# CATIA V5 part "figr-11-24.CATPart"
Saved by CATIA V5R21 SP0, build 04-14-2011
Part number: Part1
Bounding box of the stored display mesh (mm): x -89.703 to 75.958, y -127.286 to 108.862, z -26.487 to 19.815
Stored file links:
  D:\CATIA V5R21 E-RESOURCES\CATIA-V5R21\catia-v5r21-prt\c11-catia-v5r21-prt\c11-catia-v5r21-figr-11-24.CATPart
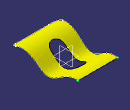
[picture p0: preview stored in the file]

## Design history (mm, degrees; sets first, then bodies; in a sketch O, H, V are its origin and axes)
Set1
  Extrude1: Element1 Sketch3, Lim1 86, Lim2 94, Direction yz-plane
  Sketch1 on xy-plane, origin (0, 0, 0), H (1, 0, 0), V (0, 1, 0)
    line L1 (64.3059, 108.8616) -> (75.9293, -106.0218)
    arc A1 centre (55.7837, -107.1115) radius 20.175 from (75.9293, -106.0218) to (55.7837, -127.2865) cw
    line L2 (55.7837, -127.2865) -> (-64.7868, -127.2865)
    arc A2 centre (-64.7868, -102.3613) radius 24.9252 from (-64.7868, -127.2865) to (-89.6873, -101.2501) cw
    line L3 (-89.6873, -101.2501) -> (-80.3115, 108.8616)
    line L4 (-80.3115, 108.8616) -> (64.3059, 108.8616)
    tangency: A1 L1, A2 L2, A2 L3, A1 L2
    horizontal: L2 H, L4 H
  Extrude2: Element1 Sketch1, Lim1 86, Lim2 94, Direction xy-plane
  Split1: ToCut Extrude1, Cutting Extrude2
  Sketch2 on xy-plane, origin (0, 0, 0), H (1, 0, 0), V (0, 1, 0)
    construction line L1 (-11.3849, 28.4134) -> (-11.3849, -36.9379)
    line L2 (12.8382, 28.4134) -> (12.8382, -36.9379)
    line L3 (-35.608, -36.9379) -> (-35.608, 28.4134)
    arc A1 centre (-11.3849, -36.9379) radius 24.2231 from (12.8382, -36.9379) to (-35.608, -36.9379) cw
    arc A2 centre (-11.3849, 28.4134) radius 24.2231 from (-35.608, 28.4134) to (12.8382, 28.4134) cw
    vertical: L1 V
    tangency: A1 L2, A2 L2, A1 L3, A2 L3
    parallelism: L1 L2
  Extrude3: Element1 Sketch2, Lim1 86, Lim2 94, Direction xy-plane
  Split2: ToCut Split1, Cutting Extrude3
  Boundary1: Boundary edge of Split2, Support Split2
Body1 (main body)
  Sketch3 on yz-plane, origin (0, 0, 0), H (0, 1, 0), V (0, 0, 1)
    spline S1 through (-130.9721, 0) (-85.5087, 19.8151) (-38.0512, 0) (0, -25.6483) (60.0541, -1.7202) (134.7951, -4.3868)
    point P1 (-130.9721, 0)
    point P2 (-38.0512, 0)
    point P3 (0, -25.6483)
    coincidence: P1 H, P2 H, P3 V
